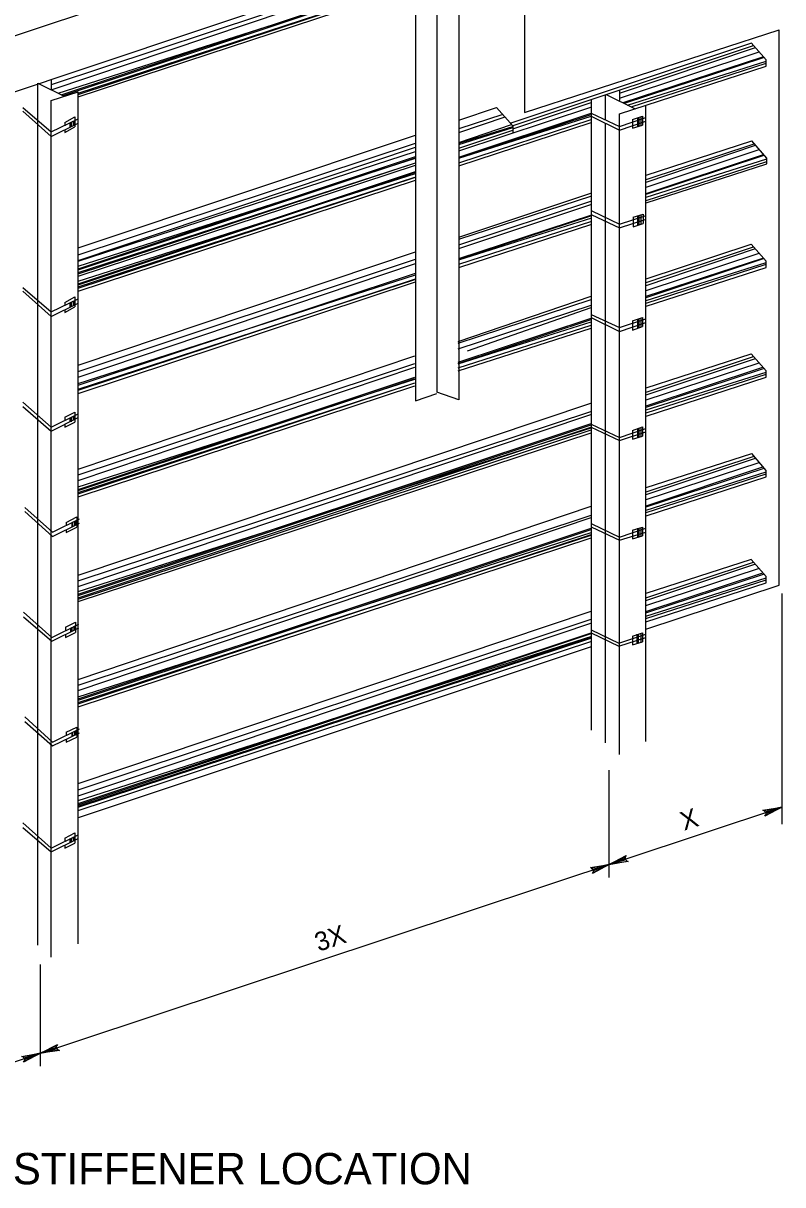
# Model space of a CAD drawing. Extents: x 650495 to 652241, y 298458 to 299646.
# Drawn here: x 650828.3 to 650949.5, y 299357.5 to 299542.7 of the extents above; entities that cross this region are included whole.
import ezdxf

# ---------------------------------------------------------------- set-up
doc = ezdxf.new("R2010")
doc.units = 0
doc.layers.add('2', color=7, linetype='Continuous')
doc.layers.add('3', color=7, linetype='Continuous')

# ---------------------------------------------------------------- blocks, each defined once
blk = doc.blocks.new('RARROW')
at = {"layer": '3'}
blk.add_lwpolyline([(-2.2695, 0.285), (-2.184875, 0.12075), (0, 0), (-2.2695, 0.285), (-2.38575, 0.384625), (0, 0), (-2.183125, -0.108), (-2.262875, -0.2705), (0, 0), (-2.38575, -0.379125), (-2.262875, -0.2705)], dxfattribs=at)

msp = doc.modelspace()

# ---------------------------------------------------------------- linework, layer by layer
at = {"layer": '2'}
for p, q in [((650805.4, 299533.47), (650908.3, 299568.07)), ((650908.3, 299568.07), (650908.3, 299528.47)), ((650809.3, 299525.87), (650904, 299557.67)), ((650904.7, 299556.77), (650832.8, 299532.87)), ((650894.3, 299553.37), (650894.3, 299483.87)), ((650832.8, 299532.07), (650890.9, 299551.67)), ((650890.9, 299552.27), (650890.9, 299482.47)), ((650897.8, 299552.27), (650897.8, 299482.67)), ((650833.9, 299531.57), (650890.9, 299549.77)), ((650834.4, 299531.27), (650890.9, 299550.07)), ((650834.7, 299531.17), (650890.9, 299549.87)), ((650837.1, 299531.57), (650890.9, 299549.17)), ((650837.1, 299531.37), (650891, 299549.17)), ((650837.1, 299530.97), (650890.9, 299548.67)), ((650908.3, 299528.47), (650948.9, 299541.67)), ((650948.9, 299453.07), (650948.9, 299541.67)), ((650906, 299526.77), (650944.5, 299539.57)), ((650946.8, 299536.87), (650944.4, 299539.57)), ((650906.3, 299526.37), (650944.8, 299539.17)), ((650923.4, 299531.57), (650945.1, 299538.87)), ((650923.4, 299530.77), (650945.7, 299538.17)), ((650923.4, 299528.27), (650946.8, 299535.87)), ((650924, 299530.07), (650946.3, 299537.37)), ((650924.2, 299529.97), (650946.4, 299537.27)), ((650924.7, 299529.67), (650946.8, 299536.67)), ((650925.3, 299529.37), (650946.8, 299536.37)), ((650946.8, 299535.87), (650946.8, 299536.87)), ((650830.7, 299533.17), (650834.9, 299531.07)), ((650830.7, 299395.67), (650830.7, 299533.17)), ((650832.8, 299533.77), (650832.8, 299532.07)), ((650832.8, 299530.37), (650837.1, 299531.77)), ((650832.8, 299393.77), (650832.8, 299530.37)), ((650837.1, 299395.87), (650837.1, 299531.77)), ((650918.9, 299530.57), (650918.9, 299429.97)), ((650921.2, 299527.27), (650921.2, 299531.37)), ((650921.3, 299531.37), (650925.9, 299529.07)), ((650923.4, 299531.97), (650923.4, 299530.37)), ((650828.3, 299529.27), (650832.8, 299525.37)), ((650828.3, 299528.67), (650832.8, 299524.67)), ((650897.8, 299522.37), (650919, 299529.37)), ((650897.8, 299527.27), (650903.8, 299529.27)), ((650903.8, 299529.27), (650906.4, 299526.37)), ((650906.4, 299525.87), (650918.9, 299530.07)), ((650927.6, 299428.17), (650927.6, 299529.67)), ((650832.8, 299525.37), (650837.1, 299527.47)), ((650832.8, 299524.67), (650837.1, 299526.77)), ((650835, 299526.87), (650836.6, 299527.77)), ((650835, 299526.87), (650835, 299526.37)), ((650835.8, 299526.87), (650835.8, 299526.17)), ((650836, 299526.97), (650836, 299526.27)), ((650836.3, 299527.07), (650836.3, 299526.47)), ((650836.5, 299527.17), (650836.5, 299526.57)), ((650836.6, 299527.77), (650836.6, 299526.17)), ((650897.8, 299521.37), (650918.9, 299528.37)), ((650904.8, 299528.17), (650897.8, 299525.87)), ((650897.8, 299521.17), (650918.9, 299528.17)), ((650897.8, 299521.17), (650918.9, 299527.87)), ((650897.8, 299525.27), (650905.2, 299527.77)), ((650897.8, 299520.47), (650918.9, 299527.37)), ((650897.8, 299519.97), (650918.9, 299526.87)), ((650918.9, 299528.37), (650923.4, 299526.27)), ((650918.9, 299527.87), (650923.4, 299525.67)), ((650921.2, 299427.97), (650921.2, 299526.77)), ((650923.4, 299426.07), (650923.4, 299528.27)), ((650923.4, 299526.27), (650927.6, 299527.67)), ((650923.4, 299525.67), (650927.6, 299527.07)), ((650925.5, 299527.37), (650927.1, 299527.87)), ((650925.5, 299527.37), (650925.5, 299525.97)), ((650926.3, 299527.67), (650926.3, 299526.17)), ((650926.5, 299527.67), (650926.5, 299526.27)), ((650926.8, 299527.77), (650926.8, 299526.37)), ((650927.1, 299527.87), (650927.1, 299526.47)), ((650835, 299525.27), (650836.6, 299526.17)), ((650835, 299525.77), (650835, 299525.27)), ((650837.1, 299506.87), (650890.9, 299524.87)), ((650897.8, 299523.67), (650906.2, 299526.57)), ((650897.8, 299523.57), (650906.4, 299526.27)), ((650897.8, 299523.37), (650906.4, 299526.07)), ((650897.8, 299522.77), (650906.4, 299525.67)), ((650906.4, 299526.37), (650906.4, 299525.17)), ((650925.5, 299525.97), (650927.1, 299526.47)), ((650837.1, 299505.77), (650890.9, 299523.57)), ((650837.1, 299504.87), (650890.9, 299522.97)), ((650927.7, 299518.47), (650944.5, 299523.97)), ((650927.7, 299517.77), (650944.9, 299523.47)), ((650927.7, 299517.37), (650945.1, 299523.27)), ((650946.9, 299521.17), (650944.5, 299523.97)), ((650837.1, 299504.77), (650890.9, 299522.27)), ((650837.1, 299503.57), (650890.9, 299521.47)), ((650837.1, 299503.37), (650890.9, 299521.27)), ((650837.1, 299503.97), (650890.9, 299521.17)), ((650927.7, 299516.57), (650945.7, 299522.57)), ((650927.7, 299515.57), (650946.4, 299521.77)), ((650927.7, 299515.47), (650946.5, 299521.67)), ((650927.7, 299514.97), (650946.9, 299521.07)), ((650946.9, 299520.27), (650946.9, 299521.17)), ((650837.1, 299502.77), (650890.9, 299520.47)), ((650837.1, 299502.97), (650890.9, 299520.47)), ((650837.1, 299502.37), (650890.9, 299520.07)), ((650927.7, 299514.47), (650946.9, 299520.67)), ((650927.7, 299514.07), (650946.9, 299520.27)), ((650837.1, 299501.17), (650890.9, 299519.07)), ((650837.1, 299500.97), (650890.9, 299518.97)), ((650837.1, 299501.57), (650890.9, 299518.77)), ((650837.1, 299500.47), (650890.9, 299518.17)), ((650837.1, 299500.67), (650890.8, 299518.17)), ((650837.1, 299499.97), (650890.9, 299517.67)), ((650897.8, 299508.57), (650919, 299515.67)), ((650897.8, 299508.27), (650919, 299515.17)), ((650897.8, 299507.37), (650919, 299514.37)), ((650897.8, 299506.77), (650919, 299513.87)), ((650897.8, 299505.17), (650919, 299512.17)), ((650897.8, 299505.07), (650919, 299512.07)), ((650919, 299512.77), (650923.4, 299510.67)), ((650919, 299512.17), (650923.4, 299510.07)), ((650923.4, 299510.67), (650927.7, 299512.07)), ((650925.6, 299511.77), (650927.2, 299512.27)), ((650925.6, 299511.77), (650925.6, 299510.27)), ((650926.3, 299511.97), (650926.3, 299510.57)), ((650926.5, 299512.07), (650926.5, 299510.57)), ((650926.8, 299512.17), (650926.8, 299510.67)), ((650927.2, 299512.27), (650927.2, 299510.77)), ((650897.8, 299504.97), (650919, 299511.67)), ((650897.8, 299504.27), (650919, 299511.17)), ((650897.8, 299503.77), (650919, 299510.67)), ((650923.4, 299510.07), (650927.7, 299511.47)), ((650925.6, 299510.27), (650927.2, 299510.77)), ((650837.1, 299488.17), (650890.9, 299506.27)), ((650927.7, 299501.97), (650944.4, 299507.47)), ((650927.7, 299501.37), (650944.8, 299507.07)), ((650927.7, 299500.87), (650945.1, 299506.77)), ((650946.8, 299504.77), (650944.4, 299507.47)), ((650837.1, 299487.17), (650890.9, 299505.07)), ((650837.1, 299486.27), (650890.9, 299504.37)), ((650927.7, 299500.07), (650945.7, 299506.07)), ((650927.7, 299499.17), (650946.3, 299505.27)), ((650927.7, 299498.97), (650946.4, 299505.17)), ((650927.7, 299498.47), (650946.8, 299504.57)), ((650946.8, 299503.77), (650946.8, 299504.77)), ((650837.1, 299484.97), (650890.9, 299502.87)), ((650837.1, 299485.27), (650890.9, 299502.57)), ((650927.7, 299498.07), (650946.8, 299504.27)), ((650927.7, 299497.57), (650946.8, 299503.77)), ((650837.1, 299484.17), (650890.9, 299501.97)), ((650837.1, 299484.37), (650890.8, 299501.87)), ((650837.1, 299483.67), (650890.9, 299501.47)), ((650828.3, 299500.57), (650832.8, 299496.67)), ((650828.3, 299499.97), (650832.8, 299495.97)), ((650835, 299498.17), (650836.6, 299499.07)), ((650836.6, 299499.07), (650836.6, 299497.47)), ((650897.7, 299491.97), (650918.9, 299499.17)), ((650832.8, 299496.67), (650837.1, 299498.77)), ((650832.8, 299495.97), (650837.1, 299498.07)), ((650835, 299498.17), (650835, 299497.77)), ((650835, 299496.57), (650836.6, 299497.47)), ((650835, 299497.07), (650835, 299496.57)), ((650835.8, 299498.17), (650835.8, 299497.47)), ((650836, 299498.27), (650836, 299497.57)), ((650836.3, 299498.37), (650836.3, 299497.77)), ((650836.5, 299498.47), (650836.5, 299497.87)), ((650897.7, 299491.67), (650918.9, 299498.67)), ((650897.7, 299490.77), (650918.9, 299497.77)), ((650899.2, 299490.47), (650918.9, 299497.37)), ((650897.7, 299488.67), (650918.9, 299495.67)), ((650897.7, 299488.47), (650918.9, 299495.47)), ((650918.9, 299496.27), (650923.4, 299494.17)), ((650918.9, 299495.77), (650923.4, 299493.57)), ((650923.4, 299494.17), (650927.6, 299495.57)), ((650925.5, 299495.27), (650927.1, 299495.77)), ((650925.5, 299495.27), (650925.5, 299493.77)), ((650926.3, 299495.47), (650926.3, 299494.07)), ((650926.5, 299495.57), (650926.5, 299494.17)), ((650926.8, 299495.67), (650926.8, 299494.27)), ((650927.1, 299495.77), (650927.1, 299494.37)), ((650897.7, 299488.37), (650918.9, 299495.07)), ((650897.7, 299487.77), (650918.9, 299494.57)), ((650897.7, 299487.27), (650918.9, 299494.07)), ((650923.4, 299493.57), (650927.6, 299494.97)), ((650925.5, 299493.77), (650927.1, 299494.37)), ((650837.1, 299471.57), (650890.8, 299489.67)), ((650927.7, 299484.57), (650944.4, 299489.97)), ((650927.7, 299483.87), (650944.8, 299489.57)), ((650946.8, 299487.27), (650944.4, 299489.97)), ((650837.1, 299470.67), (650890.8, 299488.47)), ((650837.1, 299469.77), (650890.8, 299487.87)), ((650927.7, 299483.47), (650945.1, 299489.27)), ((650927.7, 299482.67), (650945.7, 299488.57)), ((650927.7, 299481.67), (650946.3, 299487.87)), ((650837.1, 299468.37), (650890.8, 299486.27)), ((650837.1, 299468.17), (650890.8, 299486.07)), ((650837.1, 299468.77), (650890.8, 299485.97)), ((650927.7, 299481.47), (650946.4, 299487.67)), ((650927.7, 299481.07), (650946.8, 299487.07)), ((650927.7, 299480.57), (650946.8, 299486.77)), ((650927.7, 299480.07), (650946.8, 299486.27)), ((650946.8, 299486.27), (650946.8, 299487.27)), ((650837.1, 299467.67), (650890.8, 299485.37)), ((650837.1, 299467.87), (650890.8, 299485.37)), ((650837.1, 299467.17), (650890.8, 299484.87)), ((650828.3, 299482.27), (650832.8, 299478.27)), ((650837.1, 299454.67), (650919, 299482.17)), ((650890.9, 299482.47), (650894.3, 299483.67)), ((650897.8, 299482.67), (650894.3, 299483.87)), ((650828.3, 299481.57), (650832.8, 299477.67)), ((650832.8, 299478.27), (650837, 299480.37)), ((650835, 299479.87), (650836.6, 299480.67)), ((650836.6, 299480.67), (650836.6, 299479.07)), ((650837.1, 299453.77), (650919, 299480.87)), ((650837.1, 299452.87), (650919, 299480.37)), ((650832.8, 299477.67), (650837, 299479.77)), ((650835, 299479.87), (650835, 299479.37)), ((650835, 299478.27), (650836.6, 299479.07)), ((650835, 299478.67), (650835, 299478.27)), ((650835.8, 299479.77), (650835.8, 299479.17)), ((650836, 299479.87), (650836, 299479.17)), ((650836.3, 299479.97), (650836.3, 299479.37)), ((650836.5, 299480.07), (650836.5, 299479.47)), ((650837.1, 299451.67), (650918.9, 299478.87)), ((650837.1, 299451.47), (650918.9, 299478.67)), ((650918.9, 299478.77), (650923.4, 299476.67)), ((650837.1, 299451.07), (650919, 299478.37)), ((650837.1, 299452.07), (650918.9, 299478.17)), ((650837.1, 299450.87), (650918.9, 299477.87)), ((650837.1, 299450.47), (650918.9, 299477.37)), ((650918.9, 299478.27), (650923.4, 299476.17)), ((650923.4, 299476.67), (650927.6, 299478.07)), ((650923.4, 299476.17), (650927.6, 299477.57)), ((650925.5, 299477.77), (650927.1, 299478.37)), ((650925.5, 299477.77), (650925.5, 299476.37)), ((650925.5, 299476.37), (650927.1, 299476.87)), ((650926.3, 299478.07), (650926.3, 299476.57)), ((650926.5, 299478.07), (650926.5, 299476.67)), ((650926.8, 299478.27), (650926.8, 299476.77)), ((650927.1, 299478.37), (650927.1, 299476.87)), ((650927.7, 299468.67), (650944.5, 299474.07)), ((650927.7, 299467.97), (650944.9, 299473.67)), ((650927.7, 299467.57), (650945.1, 299473.37)), ((650946.8, 299471.37), (650944.5, 299474.07)), ((650927.7, 299466.77), (650945.7, 299472.67)), ((650927.7, 299465.77), (650946.3, 299471.97)), ((650927.7, 299465.57), (650946.5, 299471.77)), ((650927.7, 299465.07), (650946.8, 299471.17)), ((650946.8, 299470.37), (650946.8, 299471.37)), ((650927.7, 299464.67), (650946.8, 299470.87)), ((650927.7, 299464.17), (650946.8, 299470.37)), ((650828.6, 299465.47), (650833, 299461.57)), ((650837.1, 299438.07), (650918.9, 299465.67)), ((650828.6, 299464.87), (650833, 299460.87)), ((650833, 299461.57), (650837.3, 299463.67)), ((650835.2, 299463.07), (650836.9, 299463.97)), ((650836.9, 299463.97), (650836.9, 299462.37)), ((650837.1, 299437.17), (650918.9, 299464.27)), ((650837.1, 299436.27), (650918.9, 299463.87)), ((650833, 299460.87), (650837.3, 299462.97)), ((650835.2, 299463.07), (650835.2, 299462.57)), ((650835.2, 299461.47), (650836.9, 299462.37)), ((650835.2, 299461.97), (650835.2, 299461.47)), ((650836.1, 299463.07), (650836.1, 299462.37)), ((650836.2, 299463.17), (650836.2, 299462.47)), ((650836.5, 299463.27), (650836.5, 299462.67)), ((650836.7, 299463.37), (650836.7, 299462.67)), ((650837.1, 299434.97), (650918.9, 299462.17)), ((650837.1, 299434.77), (650918.9, 299461.97)), ((650919, 299462.87), (650923.4, 299460.77)), ((650919, 299462.37), (650923.4, 299460.27)), ((650923.4, 299460.77), (650927.6, 299462.17)), ((650925.5, 299461.87), (650927.1, 299462.37)), ((650925.5, 299461.87), (650925.5, 299460.47)), ((650926.3, 299462.17), (650926.3, 299460.67)), ((650926.5, 299462.17), (650926.5, 299460.77)), ((650926.8, 299462.27), (650926.8, 299460.87)), ((650927.1, 299462.37), (650927.1, 299460.97)), ((650837.1, 299435.27), (650918.9, 299461.47)), ((650837.1, 299434.17), (650918.9, 299461.17)), ((650837.1, 299434.37), (650918.9, 299461.07)), ((650837.1, 299433.67), (650918.9, 299460.67)), ((650923.4, 299460.27), (650927.6, 299461.57)), ((650925.5, 299460.47), (650927.1, 299460.97)), ((650944.4, 299457.17), (650927.6, 299451.77)), ((650927.6, 299451.07), (650944.8, 299456.77)), ((650927.6, 299450.67), (650945, 299456.47)), ((650946.8, 299454.47), (650944.4, 299457.17)), ((650927.6, 299449.87), (650945.6, 299455.77)), ((650927.6, 299448.87), (650946.3, 299455.07)), ((650927.6, 299448.67), (650946.4, 299454.87)), ((650946.8, 299454.47), (650946.8, 299454.47)), ((650946.8, 299453.47), (650946.8, 299454.47)), ((650927.6, 299448.17), (650946.8, 299454.27)), ((650927.6, 299447.77), (650946.8, 299453.97)), ((650927.6, 299447.27), (650946.8, 299453.47)), ((650927.6, 299446.07), (650948.9, 299453.07)), ((650927.6, 299451.77), (650927.6, 299451.77)), ((650949.3, 299451.77), (650949.3, 299414.97)), ((650837.1, 299421.47), (650918.9, 299448.97)), ((650828.4, 299448.77), (650832.9, 299444.77)), ((650828.4, 299448.07), (650832.9, 299444.17)), ((650835.1, 299446.37), (650836.7, 299447.17)), ((650836.7, 299447.17), (650836.7, 299445.57)), ((650837.1, 299420.47), (650918.9, 299447.67)), ((650837.1, 299419.47), (650919, 299447.07)), ((650832.9, 299444.77), (650837.2, 299446.87)), ((650832.9, 299444.17), (650837.2, 299446.27)), ((650835.1, 299446.37), (650835.1, 299445.87)), ((650835.1, 299444.77), (650836.7, 299445.57)), ((650835.1, 299445.27), (650835.1, 299444.77)), ((650835.9, 299446.27), (650835.9, 299445.67)), ((650836.1, 299446.37), (650836.1, 299445.77)), ((650836.4, 299446.57), (650836.4, 299445.87)), ((650836.6, 299446.67), (650836.6, 299445.97)), ((650837.1, 299418.27), (650918.9, 299445.47)), ((650837.1, 299418.07), (650918.9, 299445.37)), ((650918.9, 299445.97), (650923.3, 299443.87)), ((650918.9, 299445.47), (650923.3, 299443.37)), ((650923.3, 299443.87), (650927.6, 299445.27)), ((650925.5, 299444.97), (650927.1, 299445.47)), ((650926.2, 299445.27), (650926.2, 299443.77)), ((650926.4, 299445.27), (650926.4, 299443.87)), ((650926.8, 299445.37), (650926.8, 299443.97)), ((650927.1, 299445.47), (650927.1, 299444.07)), ((650837.1, 299418.77), (650919, 299444.97)), ((650837.1, 299417.87), (650919, 299444.87)), ((650837.1, 299417.67), (650919, 299444.67)), ((650837.1, 299417.17), (650919, 299444.17)), ((650918.9, 299443.27), (650837.1, 299415.97)), ((650923.3, 299443.37), (650927.6, 299444.77)), ((650925.5, 299444.97), (650925.5, 299443.57)), ((650925.5, 299443.57), (650927.1, 299444.07)), ((650828.6, 299432.07), (650833, 299428.07)), ((650828.6, 299431.37), (650833, 299427.47)), ((650835.2, 299429.67), (650836.9, 299430.47)), ((650836.9, 299430.47), (650836.9, 299428.87)), ((650833, 299428.07), (650837.3, 299430.17)), ((650833, 299427.47), (650837.3, 299429.57)), ((650835.2, 299429.67), (650835.2, 299429.17)), ((650835.2, 299428.07), (650836.9, 299428.87)), ((650835.2, 299428.47), (650835.2, 299428.07)), ((650836.1, 299429.57), (650836.1, 299428.97)), ((650836.2, 299429.67), (650836.2, 299428.97)), ((650836.5, 299429.77), (650836.5, 299429.17)), ((650836.7, 299429.87), (650836.7, 299429.27)), ((650921.8, 299406.47), (650921.8, 299423.57)), ((650805.9, 299370.07), (650949.3, 299417.67)), ((650828.3, 299415.17), (650832.8, 299411.17)), ((650828.3, 299414.47), (650832.8, 299410.57)), ((650832.8, 299411.17), (650837.1, 299413.27)), ((650832.8, 299410.57), (650837.1, 299412.67)), ((650835, 299412.77), (650836.6, 299413.57)), ((650835, 299412.77), (650835, 299412.27)), ((650835, 299411.17), (650836.6, 299411.97)), ((650835.8, 299412.67), (650835.8, 299412.07)), ((650836, 299412.77), (650836, 299412.07)), ((650836.3, 299412.97), (650836.3, 299412.27)), ((650836.5, 299412.97), (650836.5, 299412.37)), ((650836.6, 299413.57), (650836.6, 299411.97)), ((650835, 299411.57), (650835, 299411.17)), ((650921.8, 299408.47), (650921.8, 299408.47)), ((650831.1, 299376.37), (650831.1, 299392.57)), ((650831.1, 299378.37), (650831.1, 299378.37))]:
    msp.add_line(p, q, dxfattribs=at)

# ---------------------------------------------------------------- block references
for p, xscale, yscale, rotation in [((650949.3, 299417.67), 1.2574347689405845, 1.3092961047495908, 18.420074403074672), ((650921.8, 299408.54), 1.2574347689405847, 1.3092961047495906, -161.46838935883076), ((650921.8, 299408.54), 1.2574347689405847, 1.3092961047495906, 18.934719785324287), ((650831.1, 299378.43), 1.2574347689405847, 1.3092961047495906, 18.62052730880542), ((650831.1, 299378.43), 1.2574347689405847, 1.3092961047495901, -161.8689108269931)]:
    msp.add_blockref('RARROW', p, dxfattribs=dict(at, xscale=xscale, yscale=yscale, rotation=rotation))

# ---------------------------------------------------------------- texts
for s, p in [('X', (650933.72, 299413.91)), ('3X', (650875.43, 299394.61))]:
    msp.add_text(s, height=3, rotation=18.3451, dxfattribs=at).set_placement(p)
msp.add_text('STIFFENER LOCATION', height=5, dxfattribs=at).set_placement((650826.7, 299357.54))

doc.saveas('drawing.dxf')
